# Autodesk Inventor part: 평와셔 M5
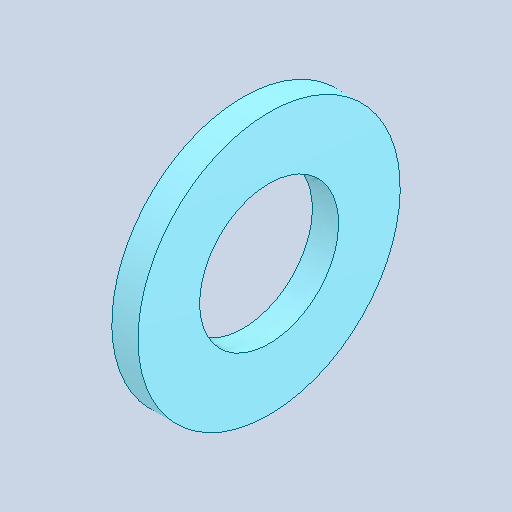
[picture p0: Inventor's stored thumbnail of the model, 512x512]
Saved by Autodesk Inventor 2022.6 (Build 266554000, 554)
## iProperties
Created: 2024-09
Part Number: 평와셔 M5
Material: 강철, 연강
Description: 평면 와셔
Document SubType Name: Modeling
Designer: Class 001
Density: 7.85 g/cm^3
Appearance: 기본값
Author: jhkim
Sending System: Autodesk Inventor 2025
Preprocessor: ST-DEVELOPER v20
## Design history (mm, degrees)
feature "Solid1"
node "솔리드1"
